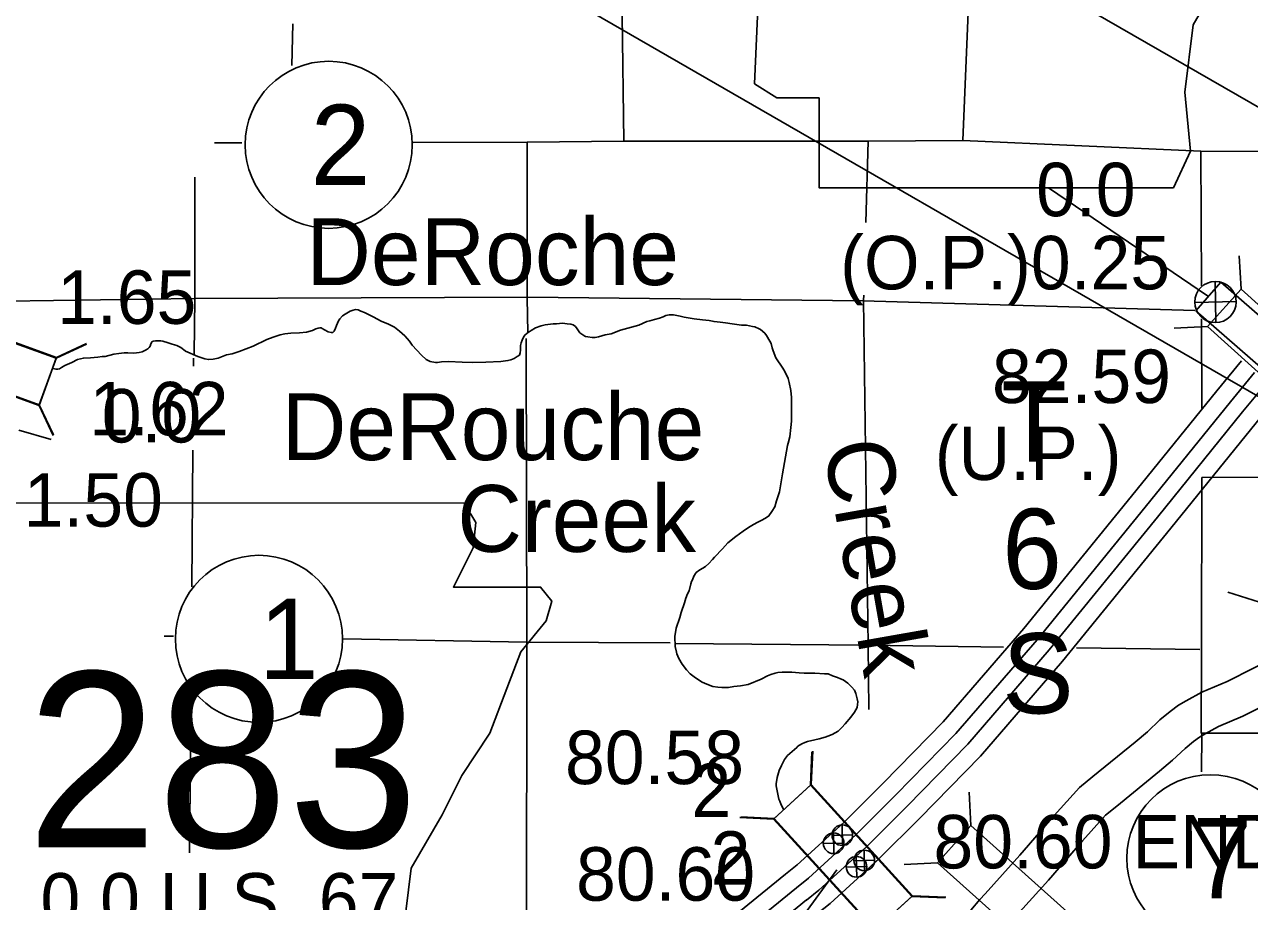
# Model space of a CAD drawing. Extents: x 369523 to 838377, y 495025 to 936819.
# Drawn here: x 582440 to 601784, y 810419 to 824276 of the extents above; entities that cross this region are included whole.
import ezdxf

# ---------------------------------------------------------------- set-up
doc = ezdxf.new("R2010")
doc.units = 0
for name, color, linetype in [('21', 7, 'Continuous'), ('22', 7, 'Continuous'), ('DSN_BRDG_Annotation', 7, 'Continuous'), ('DSN_DRFT_Common-Annotations', 7, 'Continuous'), ('DSN_DRFT_Common-Line', 7, 'Continuous'), ('DSN_DRFT_Junk-No-Plot', 7, 'Continuous'), ('Level 1', 7, 'Continuous'), ('Level 10', 7, 'Continuous'), ('Level 11', 7, 'Continuous'), ('Level 15', 7, 'Continuous'), ('Level 2', 7, 'Continuous'), ('Level 21', 7, 'Continuous'), ('Level 22', 7, 'Continuous'), ('Level 23', 7, 'Continuous'), ('Level 6', 7, 'Continuous')]:
    doc.layers.add(name, color=color, linetype=linetype)

msp = doc.modelspace()

# ---------------------------------------------------------------- linework, layer by layer
at = {"layer": '21'}
for p, q in [((459282, 905322), (715348, 757482)), ((708796, 756692), (471020, 893972)), ((598186, 815992), (598186, 815992))]:
    msp.add_line(p, q, dxfattribs=at)
msp.add_lwpolyline([(585788, 809668), (591053, 809864), (594617, 810026), (595265, 810918)], dxfattribs=at)
at = {"layer": '22'}
msp.add_line((598611, 821696), (601134, 819976), dxfattribs=at)
for points in [[(593744, 830045), (594144, 827381), (593966, 823340), (594321, 823117), (594988, 823117), (594988, 821696), (600583, 821696), (600850, 822274), (600761, 823206), (600894, 824272), (601383, 825116), (601693, 825738), (602137, 826404), (602404, 827114), (602626, 827692), (603026, 828180), (603115, 828491), (602937, 828713), (601560, 828713), (601871, 829335), (601915, 829735), (601731, 830041)], [(581396, 816718), (581796, 814054), (581618, 810012), (581973, 809790), (582639, 809790), (582639, 808369), (588235, 808369), (588501, 808946), (588413, 809879), (588546, 810945), (589034, 811789), (589345, 812410), (589789, 813077), (590056, 813787), (590278, 814364), (590677, 814853), (590766, 815164), (590589, 815386), (589212, 815386), (589523, 816008), (589567, 816407), (589383, 816714)]]:
    msp.add_lwpolyline(points, close=True, dxfattribs=at)
at = {"layer": 'DSN_DRFT_Common-Annotations'}
for p, q in [((601254, 819566), (601239, 820217)), ((600921, 819884), (601572, 819899)), ((595220, 811176), (595213, 811502)), ((595358, 811304), (595350, 811630)), ((595054, 811335), (595379, 811343)), ((595191, 811463), (595517, 811471)), ((595582, 810804), (595574, 811129)), ((595704, 810905), (595697, 811230)), ((595415, 810963), (595741, 810971)), ((595538, 811064), (595863, 811071))]:
    msp.add_line(p, q, dxfattribs=at)
for centre, radius in [((601246, 819891), 326), ((595217, 811339), 163), ((595354, 811467), 163), ((595578, 810967), 163), ((595700, 811068), 163)]:
    msp.add_circle(centre, radius, dxfattribs=at)
at = {"layer": 'DSN_DRFT_Common-Line'}
for centre in [(587244, 822375), (586142, 814569), (601167, 811103)]:
    msp.add_circle(centre, 1320, dxfattribs=at)
at = {"layer": 'Level 1'}
msp.add_line((601331, 820203), (600937, 819750), dxfattribs=at)
for points in [[(601331, 820203), (602679, 819030)], [(600937, 819750), (602285, 818577)]]:
    msp.add_lwpolyline(points, dxfattribs=at)
at = {"layer": 'Level 11'}
for points in [[(602263, 814315), (601429, 813894), (601030, 813726), (600782, 813589), (600665, 813519), (600530, 813421), (600370, 813287), (600171, 813100), (599979, 812938), (599308, 812392), (599098, 812220), (598697, 811777), (598157, 811153), (597609, 810541), (597526, 810451), (597385, 810284)], [(602537, 813782), (601681, 813349), (601292, 813185), (601083, 813069), (600995, 813017), (600898, 812947), (600769, 812839), (600570, 812652), (600361, 812476), (599687, 811926), (599512, 811784), (599146, 811379), (598608, 810757), (598054, 810138)]]:
    msp.add_lwpolyline(points, dxfattribs=at)
at = {"layer": 'Level 15'}
for points in [[(585871, 822406), (585441, 822405)], [(604283, 822285), (602548, 822267), (601017, 822274), (597259, 822443), (595760, 822433), (591904, 822430), (590377, 822417), (588577, 822412)]]:
    msp.add_lwpolyline(points, dxfattribs=at)
at = {"layer": 'Level 2'}
msp.add_lwpolyline([(606355, 817131), (601032, 817116), (601024, 814401), (601019, 813081), (605048, 813079)], dxfattribs=at)
at = {"layer": 'Level 21'}
for p, q in [((601650, 820094), (601623, 820621)), ((601120, 819505), (600593, 819478)), ((582939, 819003), (583417, 819227)), ((582943, 819014), (583421, 819238)), ((582669, 818258), (582893, 817780)), ((582673, 818269), (582897, 817791)), ((582352, 817867), (582859, 817719)), ((601943, 815150), (601439, 815308)), ((594851, 812255), (594875, 812783)), ((594863, 812266), (594887, 812794)), ((597384, 811621), (597355, 812148)), ((594265, 811722), (593738, 811746)), ((594278, 811733), (593750, 811757)), ((596856, 811031), (596329, 811002)), ((596464, 810511), (596991, 810486)), ((596451, 810499), (596979, 810475))]:
    msp.add_line(p, q, dxfattribs=at)
for points in [[(603415, 818503), (601650, 820094), (601120, 819505), (602885, 817915)], [(582939, 819003), (580705, 819812), (580435, 819068), (582669, 818258)], [(582943, 819014), (580709, 819824), (580439, 819079), (582673, 818269)], [(596451, 810499), (594851, 812255), (594265, 811722), (595866, 809966)], [(594278, 811733), (595878, 809977), (596464, 810511), (594863, 812266)], [(599154, 810036), (597384, 811621), (596856, 811031), (598626, 809446)]]:
    msp.add_lwpolyline(points, close=True, dxfattribs=at)
at = {"layer": 'Level 22'}
for points in [[(597259, 822443), (597344, 824599)], [(586661, 823626), (586676, 824289)], [(591904, 822430), (591876, 824422)], [(590377, 822417), (590379, 819952), (590390, 819409)], [(595760, 822433), (595725, 821145)], [(601017, 822274), (601025, 820145)], [(585128, 821864), (585131, 819944), (585118, 819065)], [(595693, 819998), (595690, 819921), (595764, 814465), (595770, 813455)], [(600922, 819758), (595680, 819911), (590389, 819966), (585123, 819946), (582155, 819903)], [(601027, 819625), (601032, 818212)], [(590366, 809760), (590370, 814518), (590359, 819314)], [(585108, 818876), (585109, 819005)], [(585083, 815391), (585099, 817549)], [(584790, 814611), (584645, 814609)], [(592636, 814507), (590370, 814518), (587474, 814571)], [(597899, 814440), (595754, 814467), (592708, 814498)], [(600997, 814402), (599052, 814426)], [(585047, 811189), (585069, 813762)], [(601031, 813062), (601026, 812470)]]:
    msp.add_lwpolyline(points, dxfattribs=at)
at = {"layer": 'Level 23'}
for points in [[(601658, 818963), (601268, 818487), (599922, 816822), (598218, 814732), (596947, 813258), (596003, 812296), (595384, 811675), (595047, 811368)], [(601863, 818780), (601481, 818313), (600135, 816648), (598429, 814555), (597149, 813072), (596198, 812102), (595574, 811476), (595275, 811204)], [(602040, 818601), (601675, 818155), (600329, 816491), (598620, 814394), (597334, 812903), (596376, 811927), (595747, 811295), (595452, 811027)], [(602241, 818413), (601889, 817982), (600543, 816317), (598831, 814217), (597536, 812716), (596572, 811733), (595937, 811097), (595613, 810802)], [(595370, 811663), (594641, 810998), (594459, 810852)], [(595569, 811472), (594820, 810789), (594631, 810637)], [(595729, 811280), (594983, 810599), (594787, 810442)], [(595903, 811066), (595162, 810390), (594960, 810228)], [(594457, 810850), (593718, 810250)], [(594630, 810637), (593892, 810036)], [(594788, 810443), (594050, 809842)]]:
    msp.add_lwpolyline(points, dxfattribs=at)
at = {"layer": 'Level 6'}
for points in [[(593253, 819600), (593147, 819607), (593016, 819627), (592918, 819642), (592856, 819652), (592795, 819665), (592739, 819679), (592689, 819687), (592663, 819690), (592635, 819690), (592619, 819686), (592567, 819676), (592527, 819658), (592465, 819637), (592387, 819617), (592315, 819596), (592267, 819582), (592143, 819527), (592027, 819493), (591849, 819446), (591703, 819391), (591607, 819372), (591503, 819342), (591449, 819333), (591403, 819333), (591337, 819341), (591299, 819348), (591287, 819354), (591210, 819404), (591168, 819465), (591141, 819503), (591105, 819531), (591067, 819541), (591007, 819546), (590937, 819556), (590840, 819545), (590786, 819545), (590664, 819532), (590596, 819516), (590508, 819485), (590438, 819443), (590378, 819401), (590343, 819368), (590321, 819334), (590297, 819286), (590281, 819244), (590272, 819204), (590270, 819166), (590270, 819128), (590268, 819086), (590254, 819052), (590221, 819028), (590171, 818998), (590121, 818979), (590073, 818965), (589961, 818952), (589726, 818939), (589510, 818936), (589349, 818939), (589137, 818951), (589027, 818947), (588959, 818938), (588931, 818934), (588846, 818952), (588782, 818981), (588707, 819049), (588637, 819132), (588564, 819210), (588520, 819271), (588447, 819355), (588401, 819393), (588364, 819428), (588282, 819496), (588187, 819543), (588073, 819589), (587946, 819658), (587862, 819697), (587811, 819723), (587753, 819744), (587709, 819768), (587667, 819772), (587629, 819764), (587583, 819747), (587501, 819701), (587459, 819671), (587421, 819625), (587399, 819592), (587382, 819556), (587366, 819522), (587352, 819478), (587332, 819430), (587308, 819412), (587284, 819412), (587236, 819420), (587178, 819451), (587142, 819471), (587122, 819481), (587104, 819481), (587078, 819479), (587042, 819468), (586990, 819440)], [(593253, 819600), (593147, 819607), (593016, 819627), (592918, 819642), (592856, 819652), (592795, 819665), (592739, 819679), (592689, 819687), (592663, 819690), (592635, 819690), (592619, 819686), (592567, 819676), (592527, 819658), (592465, 819637), (592387, 819617), (592315, 819596), (592267, 819582), (592143, 819527), (592027, 819493), (591849, 819446), (591703, 819391), (591607, 819372), (591503, 819342), (591449, 819333), (591403, 819333), (591337, 819341), (591299, 819348), (591287, 819354), (591210, 819404), (591168, 819465), (591141, 819503), (591105, 819531), (591067, 819541), (591007, 819546), (590937, 819556), (590840, 819545), (590786, 819545), (590664, 819532), (590596, 819516), (590508, 819485), (590438, 819443), (590378, 819401), (590343, 819368), (590321, 819334), (590297, 819286), (590281, 819244), (590272, 819204), (590270, 819166), (590270, 819128), (590268, 819086), (590254, 819052), (590221, 819028), (590171, 818998), (590121, 818979), (590073, 818965), (589961, 818952), (589726, 818939), (589510, 818936), (589349, 818939), (589137, 818951), (589027, 818947), (588959, 818938), (588931, 818934), (588846, 818952), (588782, 818981), (588707, 819049), (588637, 819132), (588564, 819210), (588520, 819271), (588447, 819355), (588401, 819393), (588364, 819428), (588282, 819496), (588187, 819543), (588073, 819589), (587946, 819658), (587862, 819697), (587811, 819723), (587753, 819744), (587709, 819768), (587667, 819772), (587629, 819764), (587583, 819747), (587501, 819701), (587459, 819671), (587421, 819625), (587399, 819592), (587382, 819556), (587366, 819522), (587352, 819478), (587332, 819430), (587308, 819412), (587284, 819412), (587236, 819420), (587178, 819451), (587142, 819471), (587122, 819481), (587104, 819481), (587078, 819479), (587042, 819468), (586990, 819440)], [(595279, 813956), (595246, 813970), (595198, 813986), (595130, 814015), (595072, 814017), (594921, 814026), (594849, 814029), (594751, 814029), (594673, 814032), (594557, 814044), (594519, 814045), (594458, 814045), (594404, 814041), (594338, 814036), (594296, 814026), (594224, 814006), (594170, 813985), (594074, 813933), (593868, 813850), (593746, 813827), (593640, 813814), (593554, 813802), (593452, 813799), (593386, 813805), (593310, 813816), (593213, 813854), (593141, 813887), (593085, 813921), (593012, 813970), (592950, 814014), (592893, 814078), (592826, 814169), (592772, 814261), (592741, 814330), (592733, 814360), (592712, 814448), (592709, 814608), (592729, 814736), (592786, 814906), (592807, 814986), (592862, 815137), (592884, 815211), (592910, 815279), (592933, 815329), (592963, 815439), (592974, 815473), (592986, 815503), (593008, 815559), (593048, 815617), (593106, 815660), (593153, 815688), (593195, 815714), (593247, 815761), (593305, 815821), (593337, 815859), (593460, 815992), (593544, 816084), (593671, 816185), (593789, 816272), (593873, 816328), (593949, 816374), (594021, 816411), (594096, 816451), (594158, 816484), (594196, 816512), (594240, 816580), (594289, 816656), (594315, 816752), (594364, 816893), (594408, 817177), (594486, 817623), (594500, 817661), (594523, 817761), (594542, 817907), (594551, 818009), (594554, 818177), (594552, 818305), (594549, 818385), (594542, 818493), (594517, 818618), (594497, 818684), (594446, 818792), (594412, 818844), (594305, 819009), (594260, 819122), (594245, 819168), (594229, 819234), (594211, 819270), (594158, 819364), (594130, 819398), (594061, 819459), (594043, 819467), (593973, 819498), (593933, 819506), (593840, 819526), (593762, 819527), (593616, 819546), (593510, 819562), (593423, 819575), (593329, 819581), (593253, 819600)], [(595279, 813956), (595246, 813970), (595198, 813986), (595130, 814015), (595072, 814017), (594921, 814026), (594849, 814029), (594751, 814029), (594673, 814032), (594557, 814044), (594519, 814045), (594458, 814045), (594404, 814041), (594338, 814036), (594296, 814026), (594224, 814006), (594170, 813985), (594074, 813933), (593868, 813850), (593746, 813827), (593640, 813814), (593554, 813802), (593452, 813799), (593386, 813805), (593310, 813816), (593213, 813854), (593141, 813887), (593085, 813921), (593012, 813970), (592950, 814014), (592893, 814078), (592826, 814169), (592772, 814261), (592741, 814330), (592733, 814360), (592712, 814448), (592709, 814608), (592729, 814736), (592786, 814906), (592807, 814986), (592862, 815137), (592884, 815211), (592910, 815279), (592933, 815329), (592963, 815439), (592974, 815473), (592986, 815503), (593008, 815559), (593048, 815617), (593106, 815660), (593153, 815688), (593195, 815714), (593247, 815761), (593305, 815821), (593337, 815859), (593460, 815992), (593544, 816084), (593671, 816185), (593789, 816272), (593873, 816328), (593949, 816374), (594021, 816411), (594096, 816451), (594158, 816484), (594196, 816512), (594240, 816580), (594289, 816656), (594315, 816752), (594364, 816893), (594408, 817177), (594486, 817623), (594500, 817661), (594523, 817761), (594542, 817907), (594551, 818009), (594554, 818177), (594552, 818305), (594549, 818385), (594542, 818493), (594517, 818618), (594497, 818684), (594446, 818792), (594412, 818844), (594305, 819009), (594260, 819122), (594245, 819168), (594229, 819234), (594211, 819270), (594158, 819364), (594130, 819398), (594061, 819459), (594043, 819467), (593973, 819498), (593933, 819506), (593840, 819526), (593762, 819527), (593616, 819546), (593510, 819562), (593423, 819575), (593329, 819581), (593253, 819600)], [(586990, 819440), (586894, 819413), (586783, 819403), (586647, 819398), (586551, 819391), (586475, 819375), (586369, 819338), (586265, 819300), (586049, 819196), (585829, 819107), (585721, 819073), (585631, 819054), (585499, 819005), (585421, 818989), (585343, 818982), (585285, 818992), (585175, 819029), (584984, 819112), (584978, 819118), (584907, 819175), (584847, 819205), (584773, 819227), (584708, 819246), (584622, 819270), (584592, 819276), (584510, 819277), (584476, 819273), (584458, 819265), (584434, 819229), (584422, 819191), (584408, 819170), (584388, 819154), (584352, 819128), (584297, 819102), (584250, 819092), (584164, 819085), (584072, 819086), (584012, 819086), (583930, 819078), (583852, 819067), (583712, 819032), (583664, 819028), (583600, 819020), (583484, 819011), (583371, 819004), (583275, 818982), (583185, 818937), (583078, 818887), (583026, 818856), (582994, 818838), (582962, 818830), (582936, 818832), (582887, 818843)], [(586990, 819440), (586894, 819413), (586783, 819403), (586647, 819398), (586551, 819391), (586475, 819375), (586369, 819338), (586265, 819300), (586049, 819196), (585829, 819107), (585721, 819073), (585631, 819054), (585499, 819005), (585421, 818989), (585343, 818982), (585285, 818992), (585175, 819029), (584984, 819112), (584978, 819118), (584907, 819175), (584847, 819205), (584773, 819227), (584708, 819246), (584622, 819270), (584592, 819276), (584510, 819277), (584476, 819273), (584458, 819265), (584434, 819229), (584422, 819191), (584408, 819170), (584388, 819154), (584352, 819128), (584297, 819102), (584250, 819092), (584164, 819085), (584072, 819086), (584012, 819086), (583930, 819078), (583852, 819067), (583712, 819032), (583664, 819028), (583600, 819020), (583484, 819011), (583371, 819004), (583275, 818982), (583185, 818937), (583078, 818887), (583026, 818856), (582994, 818838), (582962, 818830), (582936, 818832), (582891, 818842)], [(594416, 811896), (594388, 811944), (594365, 812002), (594353, 812036), (594308, 812247), (594309, 812279), (594325, 812379), (594333, 812413), (594358, 812491), (594394, 812568), (594443, 812664), (594489, 812724), (594636, 812855), (594654, 812871), (594714, 812909), (594764, 812930), (594804, 812948), (594918, 812971), (594988, 812987), (595082, 813016), (595124, 813030), (595192, 813056), (595288, 813113), (595346, 813171), (595401, 813225), (595489, 813330), (595547, 813410), (595586, 813486), (595596, 813530), (595598, 813576), (595589, 813624), (595567, 813706), (595544, 813758), (595506, 813808), (595439, 813869), (595365, 813923), (595325, 813936), (595279, 813956)], [(594427, 811877), (594388, 811944), (594365, 812002), (594353, 812036), (594308, 812247), (594309, 812279), (594325, 812379), (594333, 812413), (594358, 812491), (594394, 812568), (594443, 812664), (594489, 812724), (594636, 812855), (594654, 812871), (594714, 812909), (594764, 812930), (594804, 812948), (594918, 812971), (594988, 812987), (595082, 813016), (595124, 813030), (595192, 813056), (595288, 813113), (595346, 813171), (595401, 813225), (595489, 813330), (595547, 813410), (595586, 813486), (595596, 813530), (595598, 813576), (595589, 813624), (595567, 813706), (595544, 813758), (595506, 813808), (595439, 813869), (595365, 813923), (595325, 813936), (595279, 813956)]]:
    msp.add_lwpolyline(points, dxfattribs=at)

# ---------------------------------------------------------------- texts
at = {"layer": '21'}
for s, p in [('T', (597863, 817370)), ('6', (597879, 815358)), ('S', (597879, 813391))]:
    msp.add_text(s, height=1267, dxfattribs=at).set_placement(p)
at = {"layer": '22'}
msp.add_text('283', height=2772, dxfattribs=at).set_placement((582476, 811275))
at = {"layer": 'DSN_BRDG_Annotation'}
for s, p in [('0.0', (598415, 821247)), ('1.65', (582954, 819546)), ('0.0', (583659, 817672)), ('80.60 END', (596793, 810942)), ('80.60', (591149, 810432)), ('0.0 U.S. 67', (582692, 810023))]:
    msp.add_text(s, height=844.8, dxfattribs=at).set_placement(p)
at = {"layer": 'DSN_DRFT_Common-Line'}
for s, p in [('2', (586960, 821742)), ('1', (586142, 813935)), ('7', (600884, 810470))]:
    msp.add_text(s, height=1267, dxfattribs=at).set_placement(p)
at = {"layer": 'DSN_DRFT_Junk-No-Plot'}
for s, p in [('(O.P.)0.25', (595319, 820091)), ('82.59', (597717, 818295)), ('1.62', (583463, 817784)), ('(U.P.)', (596813, 817079)), ('1.50', (582426, 816342)), ('80.58', (590975, 812274))]:
    msp.add_text(s, height=844.8, dxfattribs=at).set_placement(p)
at = {"layer": 'Level 10'}
for s, p in [('DeRoche', (586889, 820159)), ('DeRouche', (586503, 817394)), ('Creek', (589275, 815943))]:
    msp.add_text(s, height=1056, dxfattribs=at).set_placement(p)
msp.add_text('Creek', height=1056, rotation=280, dxfattribs=at).set_placement((595049, 817636))
at = {"layer": 'Level 21'}
for p in [(592970, 811755), (593274, 810683)]:
    msp.add_text('2', height=845, dxfattribs=at).set_placement(p)

doc.saveas('drawing.dxf')
